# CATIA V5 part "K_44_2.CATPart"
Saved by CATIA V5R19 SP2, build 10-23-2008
Part number: 44_2
Publications: "Arête"
Bounding box of the stored display mesh (mm): x -160 to 160, y -50 to 50, z -30 to 30
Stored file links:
  G:\Khaled_CFAO_2011\ST2M\ST2M_GR1\mponsin\Khaled\CAD_ThinkMOTION\K_44_2.CATPart
  C:\Users\Socar\Documents\thinkmotion\Final\Diff2.CATProduct
  G:\Khaled_CFAO_2011\ST2M\ST2M_GR1\mponsin\Khaled\CAD_ThinkMOTION\K_mponsin.CATProduct
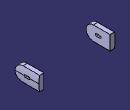
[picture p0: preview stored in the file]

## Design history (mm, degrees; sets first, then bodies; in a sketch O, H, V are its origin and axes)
External parameters (linked from other documents)
  `External.R appui` = 30 mm
  External.Lappui = 50 mm
  External.Rmeplat = 5 mm
  External.Lmeplat = 25 mm
  `External.R interne` = 160 mm
Set1
  Plane1: linked copy from another document
  Plane2 "interface 11/V": linked copy from another document
  Plane3: linked copy from another document
  Line1 "axe general": linked copy from another document
Body1 (main body)
  Sketch1 on Plane1, origin (-138.9213, 0, 0), H (0, 1, 0), V (0, 0, 1)
    line L1 (50, 30) -> (-20, 30)
    line L2 (-20, -30) -> (50, -30)
    line L3 (50, -30) -> (50, 30)
    point P3 (-20, -30)
    axis line L4 (-20, 30) -> (-20, -30)
    arc A1 centre (-20, 0) radius 30 from (-20, 30) to (-20, -30) ccw
    point P5 (-20, 0)
    point P6 (-20, -30)
    reference intersected line E1 through (50, 0) direction (0, 1) from Plane2
    line L5 (0, 5) -> (-7.5, 5)
    point P7 (0, 5)
    point P8 (-7.5, 5)
    arc A2 centre (-7.5, 0) radius 5 from (-7.5, 5) to (-12.5, 0) ccw
    point P9 (-7.5, 0)
    point P10 (-12.5, 0)
    point P11 (-7.5, -5)
    point P12 (0, -5)
    line L6 (0, -5) -> (-7.5, -5)
    point P13 (-12.5, 0)
    arc A3 centre (-7.5, 0) radius 5 from (-7.5, -5) to (-12.5, 0) cw
    point P15 (7.5, -5)
    point P16 (0, -5)
    line L7 (0, -5) -> (7.5, -5)
    point P17 (7.5, 5)
    point P18 (0, 5)
    line L8 (0, 5) -> (7.5, 5)
    point P19 (12.5, 0)
    arc A4 centre (7.5, 0) radius 5 from (7.5, 5) to (12.5, 0) cw
    point P21 (12.5, 0)
    arc A5 centre (7.5, 0) radius 5 from (7.5, -5) to (12.5, 0) ccw
    distance L1 H = 30 {= `External.R appui`}
    distance V A1 = 50 {= External.Lappui}
    distance L8 H = 5 {= External.Rmeplat}
    distance A5 A3 = 25 {= External.Lmeplat}
    horizontal: L1 H, L2 H, L5 H
    vertical: L3 V, L4 V
    symmetry: L2 L1 H, P8 P11 H, P7 P12 H, L5 L6 H, P10 P13 H, A2 A3 H, P11 P15 V, P12 P16 V, L6 L7 V, P8 P17 V, P7 P18 V, L5 L8 V, P10 P19 V, A2 A4 V, P13 P21 V, A3 A5 V
    midpoint: P5 L4
    tangency: A1 L1, A2 L5
    coincidence: P6 L2, L3 E1, P7 V, P9 H, P10 H, P3 P6, P7 P18, P10 P13, P12 P16, P19 P21
  Pad1: profile Sketch1, direction (1, 0, 0), up to Plane3
  Sketch2 on face of Pad1 from Sketch1.L3, origin (0, 50, 0), H (-1, 0, 0), V (0, 0, 1)
    circle A1 centre (0, 0) radius 160
    circle A2 centre (0, 0) radius 200
    radius A1 = 160 {= `External.R interne`}
    distance A2 A1 = 40
  Pocket1: profile Sketch2, direction (0, -1, 0), through (limit type 3)
  CircPattern1: of the body so far, instances 2, angular step 180, axis from Line1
